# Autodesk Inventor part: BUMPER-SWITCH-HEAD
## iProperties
Created: 2007-08
Part Number: BUMPER-SWITCH-HEAD
Material: ABS Plastic
Document SubType Name: Modeling
Density: 1.06 g/cm^3
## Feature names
1. Base1
